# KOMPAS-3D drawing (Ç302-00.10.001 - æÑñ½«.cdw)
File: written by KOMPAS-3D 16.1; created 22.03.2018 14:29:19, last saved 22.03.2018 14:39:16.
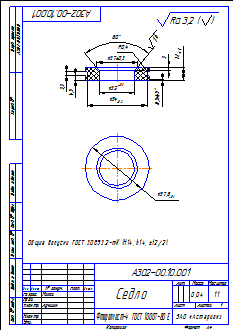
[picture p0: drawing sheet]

Sheet 1: A4, portrait

Title block, sheet 1: name: Седло; designation: А302-00.10.001; material: Фторопласт-4  ГОСТ 10007-80 Е; mass: 0,04; scale: 1:1; sheets: 1; organisation: ЗАО «Астерион»; sheet format: A4; stored path: Z:\Мембранные насосы\Мембранный электропривод\А302-00.00.000 - ASTRA-302 (МЭ200)\Чертежи\А302-00.10.001 - Седло.cdw; drawn by: Милов; technical control: Лучихин

Views: Вид 1, Местный разрез 1, Спереди, Проекционный вид 2
Referenced files in Z:\Мембранные насосы\Мембранный электропривод\А302-00.00.000 - ASTRA-302 (МЭ200)\3Д\: А302-00.10.001 - Седло.m3d
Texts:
  Общие допуски ГОСТ 30893.2-mK (H14, h14,  t2/2).
  Ra 3,2
  Ra 3,2 ( )
Dimensions and other numbers on the sheet: 12; 3,3; 32; 37±0,3; 1,6; 4,5; 0,5; 54; 0,4; 3; 57,8; 1:1; 1; 0,04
